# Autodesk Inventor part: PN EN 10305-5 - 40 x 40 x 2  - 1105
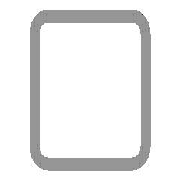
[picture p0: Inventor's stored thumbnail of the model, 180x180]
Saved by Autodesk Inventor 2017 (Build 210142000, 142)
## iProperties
IsCustomPart: 1
Created: 2016-02
Part Number: PN EN 10305-5 - 40 x 40 x 2  - 1105
Material: Stal, miękka
Description: Rury stalowe do zastosowań precyzyjnych -  (Część 5: Rury kwadratowe, spawane, wymiarowane na zimno)
Document SubType Name: Modeling
Standard: PN
Designer: X
Standards Organization: PN
Language: pl-PL
Size Designation: 40 x 40 x 2
Categories: <MemberInstance><Categories><Category DisplayName="Kształtowniki konstrukcyjne" InternalName="089c4875-fa83-4c05-b084-43b9cc11f5ed" Mnemonic="GRDR"><CategoryPar
Stock Number: 40 x 40 x 2
Density: 7.85 g/cm^3
Appearance: Częściowo polerowana
Mass: 2577.4 g
Surface Area: 3289.26 cm^2
Volume: 328.332 cm^3
_CCFamilyMember: 26
_CCFamilyDisplayName: PN EN 10305-5 (Rury kwadratowe, spawane, wymiarowane na zimno) - Rury stalowe do zastosowań precyzyjnych -  (Część 5: Rury kwadratowe, spawane, wymiarowane na z
_FrameMemberDoc: Frame Member File
_Version: 15.0.0
_GetPNFromCC: 1
G_L: 1105,000 mm
G_W: 40,000 mm
G_H: 40,000 mm
Author: X
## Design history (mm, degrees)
node "Płaszczyzna początkowa"
node "Płaszczyzna końcowa"
sketch "Szkic"
  geometry: L1 (-20, -17)-(-20, 17); L2 (-17, 20)-(17, 20); L3 (20, 17)-(20, -17); L4 (17, -20)-(-17, -20); L5 (-17, 18)-(17, 18); L6 (18, 17)-(18, -17); L7 (17, -18)-(-17, -18); L8 (-18, -17)-(-18, 17); L9 (0, 28.87)-(0, -28.87) reference; L10 (-28.87, 0)-(28.87, 0) reference; A1 r 3 centre (-17, -17) between (-20, -17) and (-17, -20); A2 r 3 centre (-17, 17) between (-17, 20) and (-20, 17); A3 r 3 centre (17, 17) between (20, 17) and (17, 20); A4 r 3 centre (17, -17) between (17, -20) and (20, -17); A5 r 1 centre (-17, 17) between (-17, 18) and (-18, 17); A6 r 1 centre (17, 17) between (18, 17) and (17, 18); A7 r 1 centre (17, -17) between (17, -18) and (18, -17); A8 r 1 centre (-17, -17) between (-18, -17) and (-17, -18)
  constraints: 16 end point, 16 point on circle, 8 centre point, 8 tangent, 4 parallel, 3 equal radius, 2 perpendicular, 7 other
  dimensions: "d7" = 3 radius of A1 (= G_IR); "d10" = 40 distance between parallel lines of L2 L4 (= G_H); "d11" = 40 distance between parallel lines of L1 L3 (= G_W); "d12" = 2 distance between parallel lines of L3 L6 (= G_T); "d15" = 20 distance between parallel lines of L2 L10 (= 0.5 x d10); "d16" = 20 distance between parallel lines of L9 L3 (= 0.5 x d11)
extrude "Bryła" new body sketch "Szkic" stored distance "d3" = 1105 (= G_L); taper "d4" = 0 deg
node "Driven Length"
  sketch "Sketch3"
    geometry: L1 (0, 0)-(10, 0) reference
    constraints: 2 end point, 1 horizontal
  workplane "Work Plane3"
  sketch "Sketch4"
    geometry: L1 (-2, 35)-(12, 35) reference; L2 (-2, 1140)-(12, 1140) reference
    dimensions: "d18" = 1105 distance between parallel lines of L1 L2 (derived)
body "Solid1"
other parameters: "G_W" = 40 [user parameter; used in 1 equation term], "G_H" = 40 [user parameter; used in 1 equation term], "G_T" = 2 [user parameter; used in 1 equation term], "G_IR" = 3 [user parameter; used in 1 equation term], "G_L" = 1105 (= d18) [user parameter; used in 1 equation term], "G_OFFSET_START" = -35 [user parameter; used in 1 equation term], "G_OFFSET_END" = 0 [user parameter; used in 1 equation term], "d13" = 35 (= -G_OFFSET_START), "d17" = 90 deg
